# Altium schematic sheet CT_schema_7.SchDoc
size 274 x 160 mm
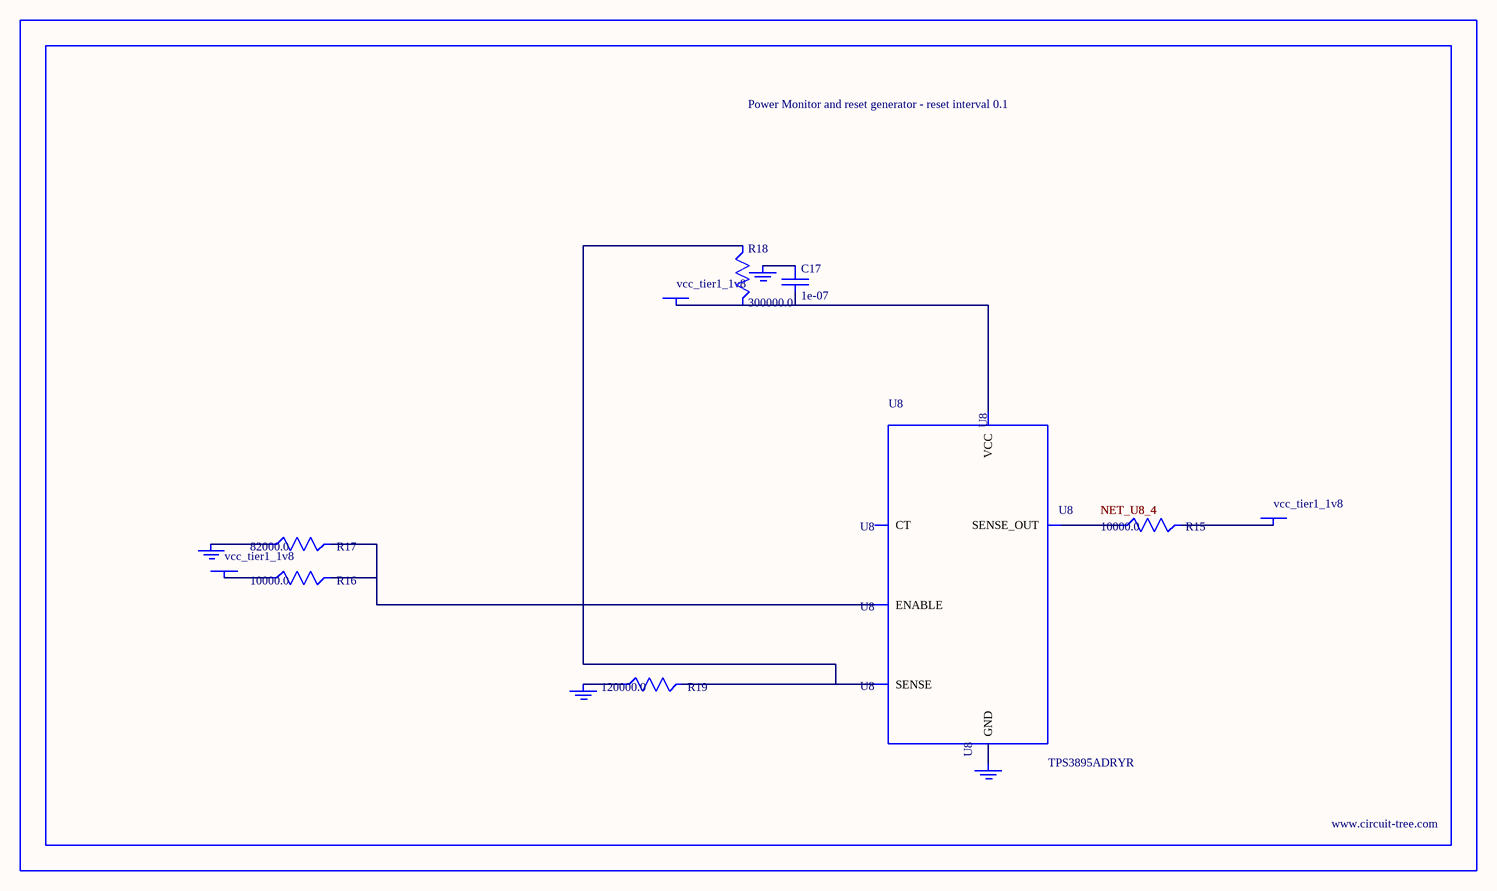
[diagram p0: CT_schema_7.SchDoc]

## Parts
BORDER6  (no value)
C17  1e-07  [C0402]
GND_INSTANCE_6_0  (no value)
GND_INSTANCE_6_1  (no value)
GND_INSTANCE_6_2  (no value)
GND_INSTANCE_6_3  (no value)
POWER_INSTANCE_6_0  vcc_tier1_1v8
POWER_INSTANCE_6_1  vcc_tier1_1v8
POWER_INSTANCE_6_2  vcc_tier1_1v8
R15  10000.0  [R0603]
R16  10000.0  [R0603]
R17  82000.0  [R0603]
R18  300000.0  [R0603]
R19  120000.0  [R0603]
U8  TPS3895ADRYR  [SON-6]

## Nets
NetC17_1: C17.1 GND_INSTANCE_6_2.0(GND)
NetC17_2: C17.2 POWER_INSTANCE_6_2.0(PWR) R18.2 U8.6(VCC)
NetGND_INSTANCE_6_0_0: GND_INSTANCE_6_0.0(GND) R17.1
NetGND_INSTANCE_6_1_0: GND_INSTANCE_6_1.0(GND) R19.1
NetGND_INSTANCE_6_3_0: GND_INSTANCE_6_3.0(GND) U8.2(GND)
NetPOWER_INSTANCE_6_0_0: POWER_INSTANCE_6_0.0(PWR) R16.1
NetPOWER_INSTANCE_6_1_0: POWER_INSTANCE_6_1.0(PWR) R15.2
NetR15_1: R15.1 U8.4(SENSE_OUT)
NetR16_2: R16.2 R17.2 U8.1(ENABLE)
NetR18_1: R18.1 R19.2 U8.3(SENSE)

Not connected (* = marked no-connect by the designer): U8 5(CT)

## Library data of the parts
BORDER6 = BORDER_PAGE6
C17 = C0402C104K3RACTU
GND_INSTANCE_6_0-GND_INSTANCE_6_3 = GND
POWER_INSTANCE_6_0-POWER_INSTANCE_6_2 = PWR
R15 R16 = RC0603JR-0710KL
R17 = RC0603JR-0782KL
R18 = RC0603JR-07300KL
R19 = RC0603JR-07120KL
